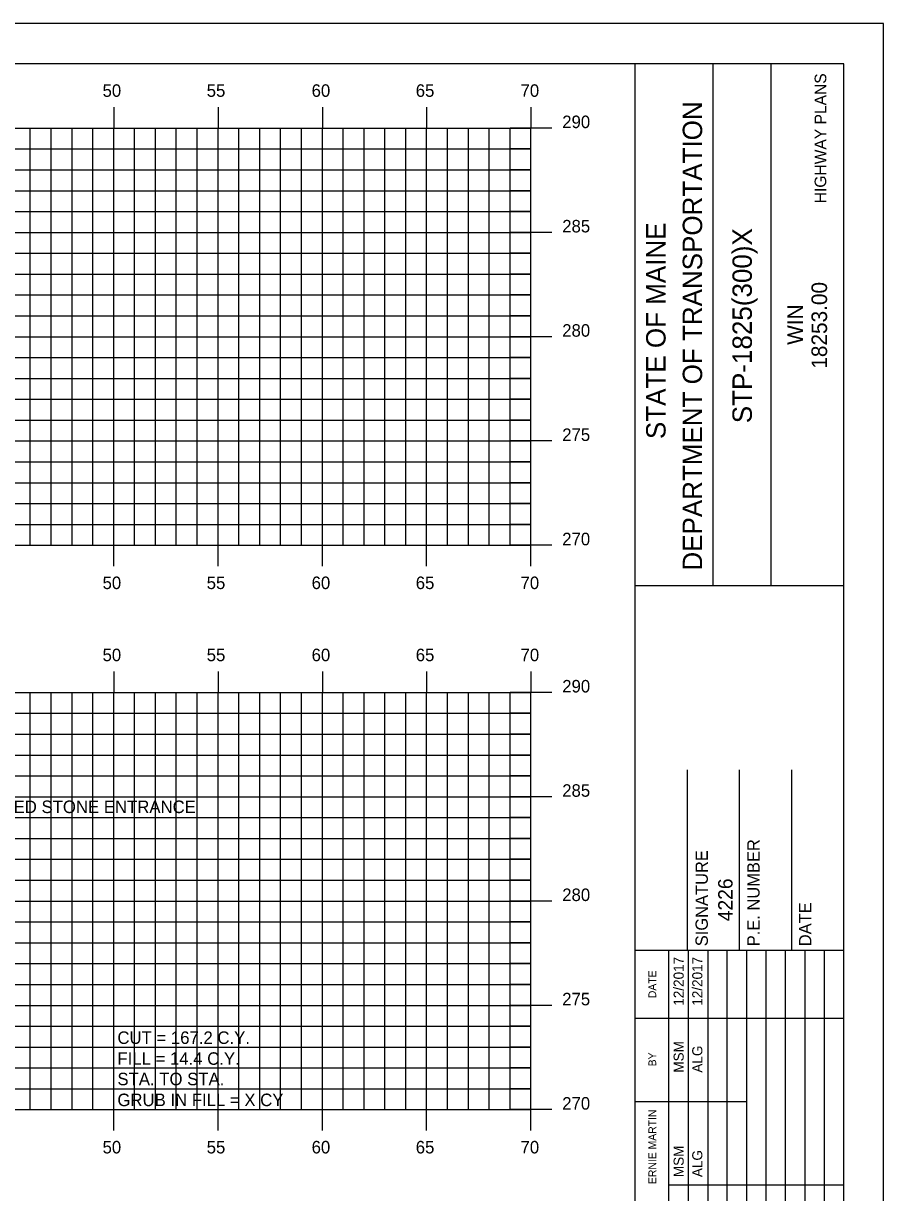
# Model space of a CAD drawing. Extents: x 853340 to 853510, y 366268 to 366378.
# Drawn here: x 853468.8 to 853510, y 366322.1 to 366378.2 of the extents above; entities that cross this region are included whole.
import ezdxf

# ---------------------------------------------------------------- set-up
doc = ezdxf.new("R2010")
doc.units = 0
for name, color, linetype in [('ANNOTATION', 7, 'Continuous'), ('BORDER', 7, 'Continuous'), ('H_V ANNOTATION', 7, 'Continuous'), ('HIGHWAY_TITLE', 7, 'Continuous'), ('MAJOR', 7, 'Continuous'), ('MINOR', 7, 'Continuous'), ('PLOT BOUNDARY', 7, 'Continuous')]:
    doc.layers.add(name, color=color, linetype=linetype)

msp = doc.modelspace()

# ---------------------------------------------------------------- linework, layer by layer
at = {"layer": 'BORDER'}
for p, q in [((853508.1, 366376.236), (853348.1, 366376.236)), ((853498.1, 366271.236), (853498.1, 366376.239)), ((853501.829, 366351.234), (853501.829, 366376.234)), ((853504.624, 366351.234), (853504.624, 366376.234)), ((853508.1, 366271.236), (853508.1, 366376.236)), ((853498.101, 366351.231), (853508.1, 366351.231)), ((853500.6, 366333.739), (853500.6, 366342.387)), ((853503.1, 366333.739), (853503.1, 366342.387)), ((853505.6, 366333.739), (853505.6, 366342.387)), ((853498.1, 366333.739), (853508.1, 366333.739))]:
    msp.add_line(p, q, dxfattribs=at)
for points in [[(853499.715, 366330.489), (853499.715, 366333.739)], [(853500.647, 366316.242), (853500.647, 366333.739)], [(853501.579, 366333.739), (853501.579, 366316.242)], [(853502.511, 366316.242), (853502.511, 366333.739)], [(853503.442, 366316.242), (853503.442, 366333.739)], [(853504.374, 366316.242), (853504.374, 366333.739)], [(853505.306, 366316.242), (853505.306, 366333.739)], [(853506.238, 366316.242), (853506.238, 366333.739)], [(853507.169, 366316.242), (853507.169, 366333.739)], [(853499.716, 366316.242), (853499.716, 366333.033)], [(853498.1, 366330.489), (853508.1, 366330.489)], [(853498.1, 366326.489), (853499.716, 366326.489)], [(853499.715, 366326.489), (853503.442, 366326.489)], [(853499.715, 366322.489), (853508.1, 366322.489)]]:
    msp.add_lwpolyline(points, dxfattribs=at)
at = {"layer": 'MAJOR'}
for p, q in [((853473.1, 366374.158), (853473.1, 366373.156)), ((853478.1, 366374.158), (853478.1, 366373.156)), ((853483.1, 366374.158), (853483.1, 366373.156)), ((853488.1, 366374.158), (853488.1, 366373.156)), ((853493.1, 366374.158), (853493.1, 366373.156)), ((853353.1, 366373.156), (853493.1, 366373.156)), ((853353.1, 366373.156), (853493.1, 366373.156)), ((853473.1, 366353.156), (853473.1, 366373.156)), ((853478.1, 366353.156), (853478.1, 366373.156)), ((853483.1, 366353.156), (853483.1, 366373.156)), ((853488.1, 366353.156), (853488.1, 366373.156)), ((853494.102, 366373.156), (853492.098, 366373.156)), ((853493.1, 366353.156), (853493.1, 366373.156)), ((853493.1, 366353.156), (853493.1, 366373.156)), ((853353.1, 366368.156), (853493.1, 366368.156)), ((853494.102, 366368.156), (853492.098, 366368.156)), ((853353.1, 366363.156), (853493.1, 366363.156)), ((853494.102, 366363.156), (853492.098, 366363.156)), ((853353.1, 366358.156), (853493.1, 366358.156)), ((853494.102, 366358.156), (853492.098, 366358.156)), ((853353.1, 366353.156), (853493.1, 366353.156)), ((853353.1, 366353.156), (853493.1, 366353.156)), ((853473.1, 366352.154), (853473.1, 366353.156)), ((853478.1, 366352.154), (853478.1, 366353.156)), ((853483.1, 366352.154), (853483.1, 366353.156)), ((853488.1, 366352.154), (853488.1, 366353.156)), ((853494.102, 366353.156), (853492.098, 366353.156)), ((853493.1, 366352.154), (853493.1, 366353.156)), ((853473.1, 366347.101), (853473.1, 366346.099)), ((853478.1, 366347.101), (853478.1, 366346.099)), ((853483.1, 366347.101), (853483.1, 366346.099)), ((853488.1, 366347.101), (853488.1, 366346.099)), ((853493.1, 366347.101), (853493.1, 366346.099)), ((853353.1, 366346.099), (853493.1, 366346.099)), ((853353.1, 366346.099), (853493.1, 366346.099)), ((853473.1, 366326.099), (853473.1, 366346.099)), ((853478.1, 366326.099), (853478.1, 366346.099)), ((853483.1, 366326.099), (853483.1, 366346.099)), ((853488.1, 366326.099), (853488.1, 366346.099)), ((853494.102, 366346.099), (853492.098, 366346.099)), ((853493.1, 366326.099), (853493.1, 366346.099)), ((853493.1, 366326.099), (853493.1, 366346.099)), ((853353.1, 366341.099), (853493.1, 366341.099)), ((853494.102, 366341.099), (853492.098, 366341.099)), ((853353.1, 366336.099), (853493.1, 366336.099)), ((853494.102, 366336.099), (853492.098, 366336.099)), ((853353.1, 366331.099), (853493.1, 366331.099)), ((853494.102, 366331.099), (853492.098, 366331.099)), ((853353.1, 366326.099), (853493.1, 366326.099)), ((853353.1, 366326.099), (853493.1, 366326.099)), ((853473.1, 366325.097), (853473.1, 366326.099)), ((853478.1, 366325.097), (853478.1, 366326.099)), ((853483.1, 366325.097), (853483.1, 366326.099)), ((853488.1, 366325.097), (853488.1, 366326.099)), ((853494.102, 366326.099), (853492.098, 366326.099)), ((853493.1, 366325.097), (853493.1, 366326.099))]:
    msp.add_line(p, q, dxfattribs=at)
at = {"layer": 'MINOR'}
for p, q in [((853469.1, 366353.156), (853469.1, 366373.156)), ((853470.1, 366353.156), (853470.1, 366373.156)), ((853471.1, 366353.156), (853471.1, 366373.156)), ((853472.1, 366353.156), (853472.1, 366373.156)), ((853474.1, 366353.156), (853474.1, 366373.156)), ((853475.1, 366353.156), (853475.1, 366373.156)), ((853476.1, 366353.156), (853476.1, 366373.156)), ((853477.1, 366353.156), (853477.1, 366373.156)), ((853479.1, 366353.156), (853479.1, 366373.156)), ((853480.1, 366353.156), (853480.1, 366373.156)), ((853481.1, 366353.156), (853481.1, 366373.156)), ((853482.1, 366353.156), (853482.1, 366373.156)), ((853484.1, 366353.156), (853484.1, 366373.156)), ((853485.1, 366353.156), (853485.1, 366373.156)), ((853486.1, 366353.156), (853486.1, 366373.156)), ((853487.1, 366353.156), (853487.1, 366373.156)), ((853489.1, 366353.156), (853489.1, 366373.156)), ((853490.1, 366353.156), (853490.1, 366373.156)), ((853491.1, 366353.156), (853491.1, 366373.156)), ((853492.1, 366353.156), (853492.1, 366373.156)), ((853353.1, 366372.156), (853493.1, 366372.156)), ((853493.1, 366372.156), (853492.098, 366372.156)), ((853353.1, 366371.156), (853493.1, 366371.156)), ((853493.1, 366371.156), (853492.098, 366371.156)), ((853353.1, 366370.156), (853493.1, 366370.156)), ((853493.1, 366370.156), (853492.098, 366370.156)), ((853353.1, 366369.156), (853493.1, 366369.156)), ((853493.1, 366369.156), (853492.098, 366369.156)), ((853353.1, 366367.156), (853493.1, 366367.156)), ((853493.1, 366367.156), (853492.098, 366367.156)), ((853353.1, 366366.156), (853493.1, 366366.156)), ((853493.1, 366366.156), (853492.098, 366366.156)), ((853353.1, 366365.156), (853493.1, 366365.156)), ((853493.1, 366365.156), (853492.098, 366365.156)), ((853353.1, 366364.156), (853493.1, 366364.156)), ((853493.1, 366364.156), (853492.098, 366364.156)), ((853353.1, 366362.156), (853493.1, 366362.156)), ((853493.1, 366362.156), (853492.098, 366362.156)), ((853353.1, 366361.156), (853493.1, 366361.156)), ((853493.1, 366361.156), (853492.098, 366361.156)), ((853353.1, 366360.156), (853493.1, 366360.156)), ((853493.1, 366360.156), (853492.098, 366360.156)), ((853353.1, 366359.156), (853493.1, 366359.156)), ((853493.1, 366359.156), (853492.098, 366359.156)), ((853353.1, 366357.156), (853493.1, 366357.156)), ((853493.1, 366357.156), (853492.098, 366357.156)), ((853353.1, 366356.156), (853493.1, 366356.156)), ((853493.1, 366356.156), (853492.098, 366356.156)), ((853353.1, 366355.156), (853493.1, 366355.156)), ((853493.1, 366355.156), (853492.098, 366355.156)), ((853353.1, 366354.156), (853493.1, 366354.156)), ((853493.1, 366354.156), (853492.098, 366354.156)), ((853469.1, 366326.099), (853469.1, 366346.099)), ((853470.1, 366326.099), (853470.1, 366346.099)), ((853471.1, 366326.099), (853471.1, 366346.099)), ((853472.1, 366326.099), (853472.1, 366346.099)), ((853474.1, 366326.099), (853474.1, 366346.099)), ((853475.1, 366326.099), (853475.1, 366346.099)), ((853476.1, 366326.099), (853476.1, 366346.099)), ((853477.1, 366326.099), (853477.1, 366346.099)), ((853479.1, 366326.099), (853479.1, 366346.099)), ((853480.1, 366326.099), (853480.1, 366346.099)), ((853481.1, 366326.099), (853481.1, 366346.099)), ((853482.1, 366326.099), (853482.1, 366346.099)), ((853484.1, 366326.099), (853484.1, 366346.099)), ((853485.1, 366326.099), (853485.1, 366346.099)), ((853486.1, 366326.099), (853486.1, 366346.099)), ((853487.1, 366326.099), (853487.1, 366346.099)), ((853489.1, 366326.099), (853489.1, 366346.099)), ((853490.1, 366326.099), (853490.1, 366346.099)), ((853491.1, 366326.099), (853491.1, 366346.099)), ((853492.1, 366326.099), (853492.1, 366346.099)), ((853353.1, 366345.099), (853493.1, 366345.099)), ((853493.1, 366345.099), (853492.098, 366345.099)), ((853353.1, 366344.099), (853493.1, 366344.099)), ((853493.1, 366344.099), (853492.098, 366344.099)), ((853353.1, 366343.099), (853493.1, 366343.099)), ((853493.1, 366343.099), (853492.098, 366343.099)), ((853353.1, 366342.099), (853493.1, 366342.099)), ((853493.1, 366342.099), (853492.098, 366342.099)), ((853353.1, 366340.099), (853493.1, 366340.099)), ((853493.1, 366340.099), (853492.098, 366340.099)), ((853353.1, 366339.099), (853493.1, 366339.099)), ((853493.1, 366339.099), (853492.098, 366339.099)), ((853353.1, 366338.099), (853493.1, 366338.099)), ((853493.1, 366338.099), (853492.098, 366338.099)), ((853353.1, 366337.099), (853493.1, 366337.099)), ((853493.1, 366337.099), (853492.098, 366337.099)), ((853353.1, 366335.099), (853493.1, 366335.099)), ((853493.1, 366335.099), (853492.098, 366335.099)), ((853353.1, 366334.099), (853493.1, 366334.099)), ((853493.1, 366334.099), (853492.098, 366334.099)), ((853353.1, 366333.099), (853493.1, 366333.099)), ((853493.1, 366333.099), (853492.098, 366333.099)), ((853353.1, 366332.099), (853493.1, 366332.099)), ((853493.1, 366332.099), (853492.098, 366332.099)), ((853353.1, 366330.099), (853493.1, 366330.099)), ((853493.1, 366330.099), (853492.098, 366330.099)), ((853353.1, 366329.099), (853493.1, 366329.099)), ((853493.1, 366329.099), (853492.098, 366329.099)), ((853353.1, 366328.099), (853493.1, 366328.099)), ((853493.1, 366328.099), (853492.098, 366328.099)), ((853353.1, 366327.099), (853493.1, 366327.099)), ((853493.1, 366327.099), (853492.098, 366327.099))]:
    msp.add_line(p, q, dxfattribs=at)
at = {"layer": 'PLOT BOUNDARY'}
msp.add_lwpolyline([(853340.007, 366268.177), (853510.007, 366268.177), (853510.007, 366378.177), (853340.007, 366378.177)], close=True, dxfattribs=at)

# ---------------------------------------------------------------- texts
at = {"layer": 'ANNOTATION'}
for s, p in [('CONSTRUCT CRUSHED STONE ENTRANCE', (853460.187, 366340.317)), ('CUT = 167.2 C.Y.', (853473.276, 366329.249)), ('FILL = 14.4 C.Y.', (853473.276, 366328.247)), ('STA. TO STA. ', (853473.276, 366327.268)), ('GRUB IN FILL = X CY ', (853473.276, 366326.266))]:
    msp.add_text(s, height=0.6, dxfattribs=at).set_placement(p)
msp.add_text('4226', height=0.69, rotation=90, dxfattribs=at).set_placement((853502.765, 366335.13))
at = {"layer": 'BORDER'}
for s, height, p in [('DEPARTMENT OF TRANSPORTATION', 0.93176, (853501.307, 366351.942)), ('STATE OF MAINE', 0.93176, (853499.555, 366358.248)), ('STP-1825(300)X', 0.93176, (853503.692, 366359.008)), ('18253.00', 0.7453, (853507.295, 366361.623)), ('WIN', 0.7453, (853506.137, 366362.766)), ('P.E. NUMBER', 0.59055, (853504.061, 366333.932)), ('SIGNATURE', 0.5906, (853501.58, 366333.932)), ('DATE', 0.5906, (853506.541, 366333.932)), ('12/2017', 0.4845, (853500.423, 366331.081)), ('12/2017', 0.4845, (853501.317, 366331.081)), ('DATE', 0.3714, (853499.104, 366331.445)), ('MSM', 0.4845, (853500.423, 366327.872)), ('ALG', 0.4845, (853501.317, 366327.872)), ('BY', 0.3714, (853499.104, 366328.174)), ('ERNIE MARTIN', 0.37275, (853499.104, 366322.531)), ('MSM', 0.4845, (853500.423, 366322.863)), ('ALG', 0.4845, (853501.317, 366322.863))]:
    msp.add_text(s, height=height, rotation=90, dxfattribs=at).set_placement(p)
at = {"layer": 'H_V ANNOTATION'}
for s, p in [('50', (853472.564, 366374.656)), ('55', (853477.556, 366374.656)), ('60', (853482.586, 366374.656)), ('65', (853487.578, 366374.656)), ('70', (853492.602, 366374.656)), ('290', (853494.6, 366373.156)), ('285', (853494.6, 366368.156)), ('280', (853494.6, 366363.156)), ('275', (853494.6, 366358.156)), ('270', (853494.6, 366353.156)), ('50', (853472.564, 366351.056)), ('55', (853477.556, 366351.056)), ('60', (853482.586, 366351.056)), ('65', (853487.578, 366351.056)), ('70', (853492.602, 366351.056)), ('50', (853472.564, 366347.599)), ('55', (853477.556, 366347.599)), ('60', (853482.586, 366347.599)), ('65', (853487.578, 366347.599)), ('70', (853492.602, 366347.599)), ('290', (853494.6, 366346.099)), ('285', (853494.6, 366341.099)), ('280', (853494.6, 366336.099)), ('275', (853494.6, 366331.099)), ('270', (853494.6, 366326.099)), ('50', (853472.564, 366323.999)), ('55', (853477.556, 366323.999)), ('60', (853482.586, 366323.999)), ('65', (853487.578, 366323.999)), ('70', (853492.602, 366323.999))]:
    msp.add_text(s, height=0.6, dxfattribs=at).set_placement(p)
at = {"layer": 'HIGHWAY_TITLE'}
msp.add_text('HIGHWAY PLANS', height=0.55901, rotation=90, dxfattribs=at).set_placement((853507.258, 366369.552))

doc.saveas('drawing.dxf')
